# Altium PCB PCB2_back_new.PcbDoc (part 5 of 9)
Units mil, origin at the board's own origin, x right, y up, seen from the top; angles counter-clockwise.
Board outline 6299 x 3937 mil, 4 copper layers (TopLayer, GROUND, VCC, BottomLayer); 253 components, 421 nets, 2085 pads, 712 vias.
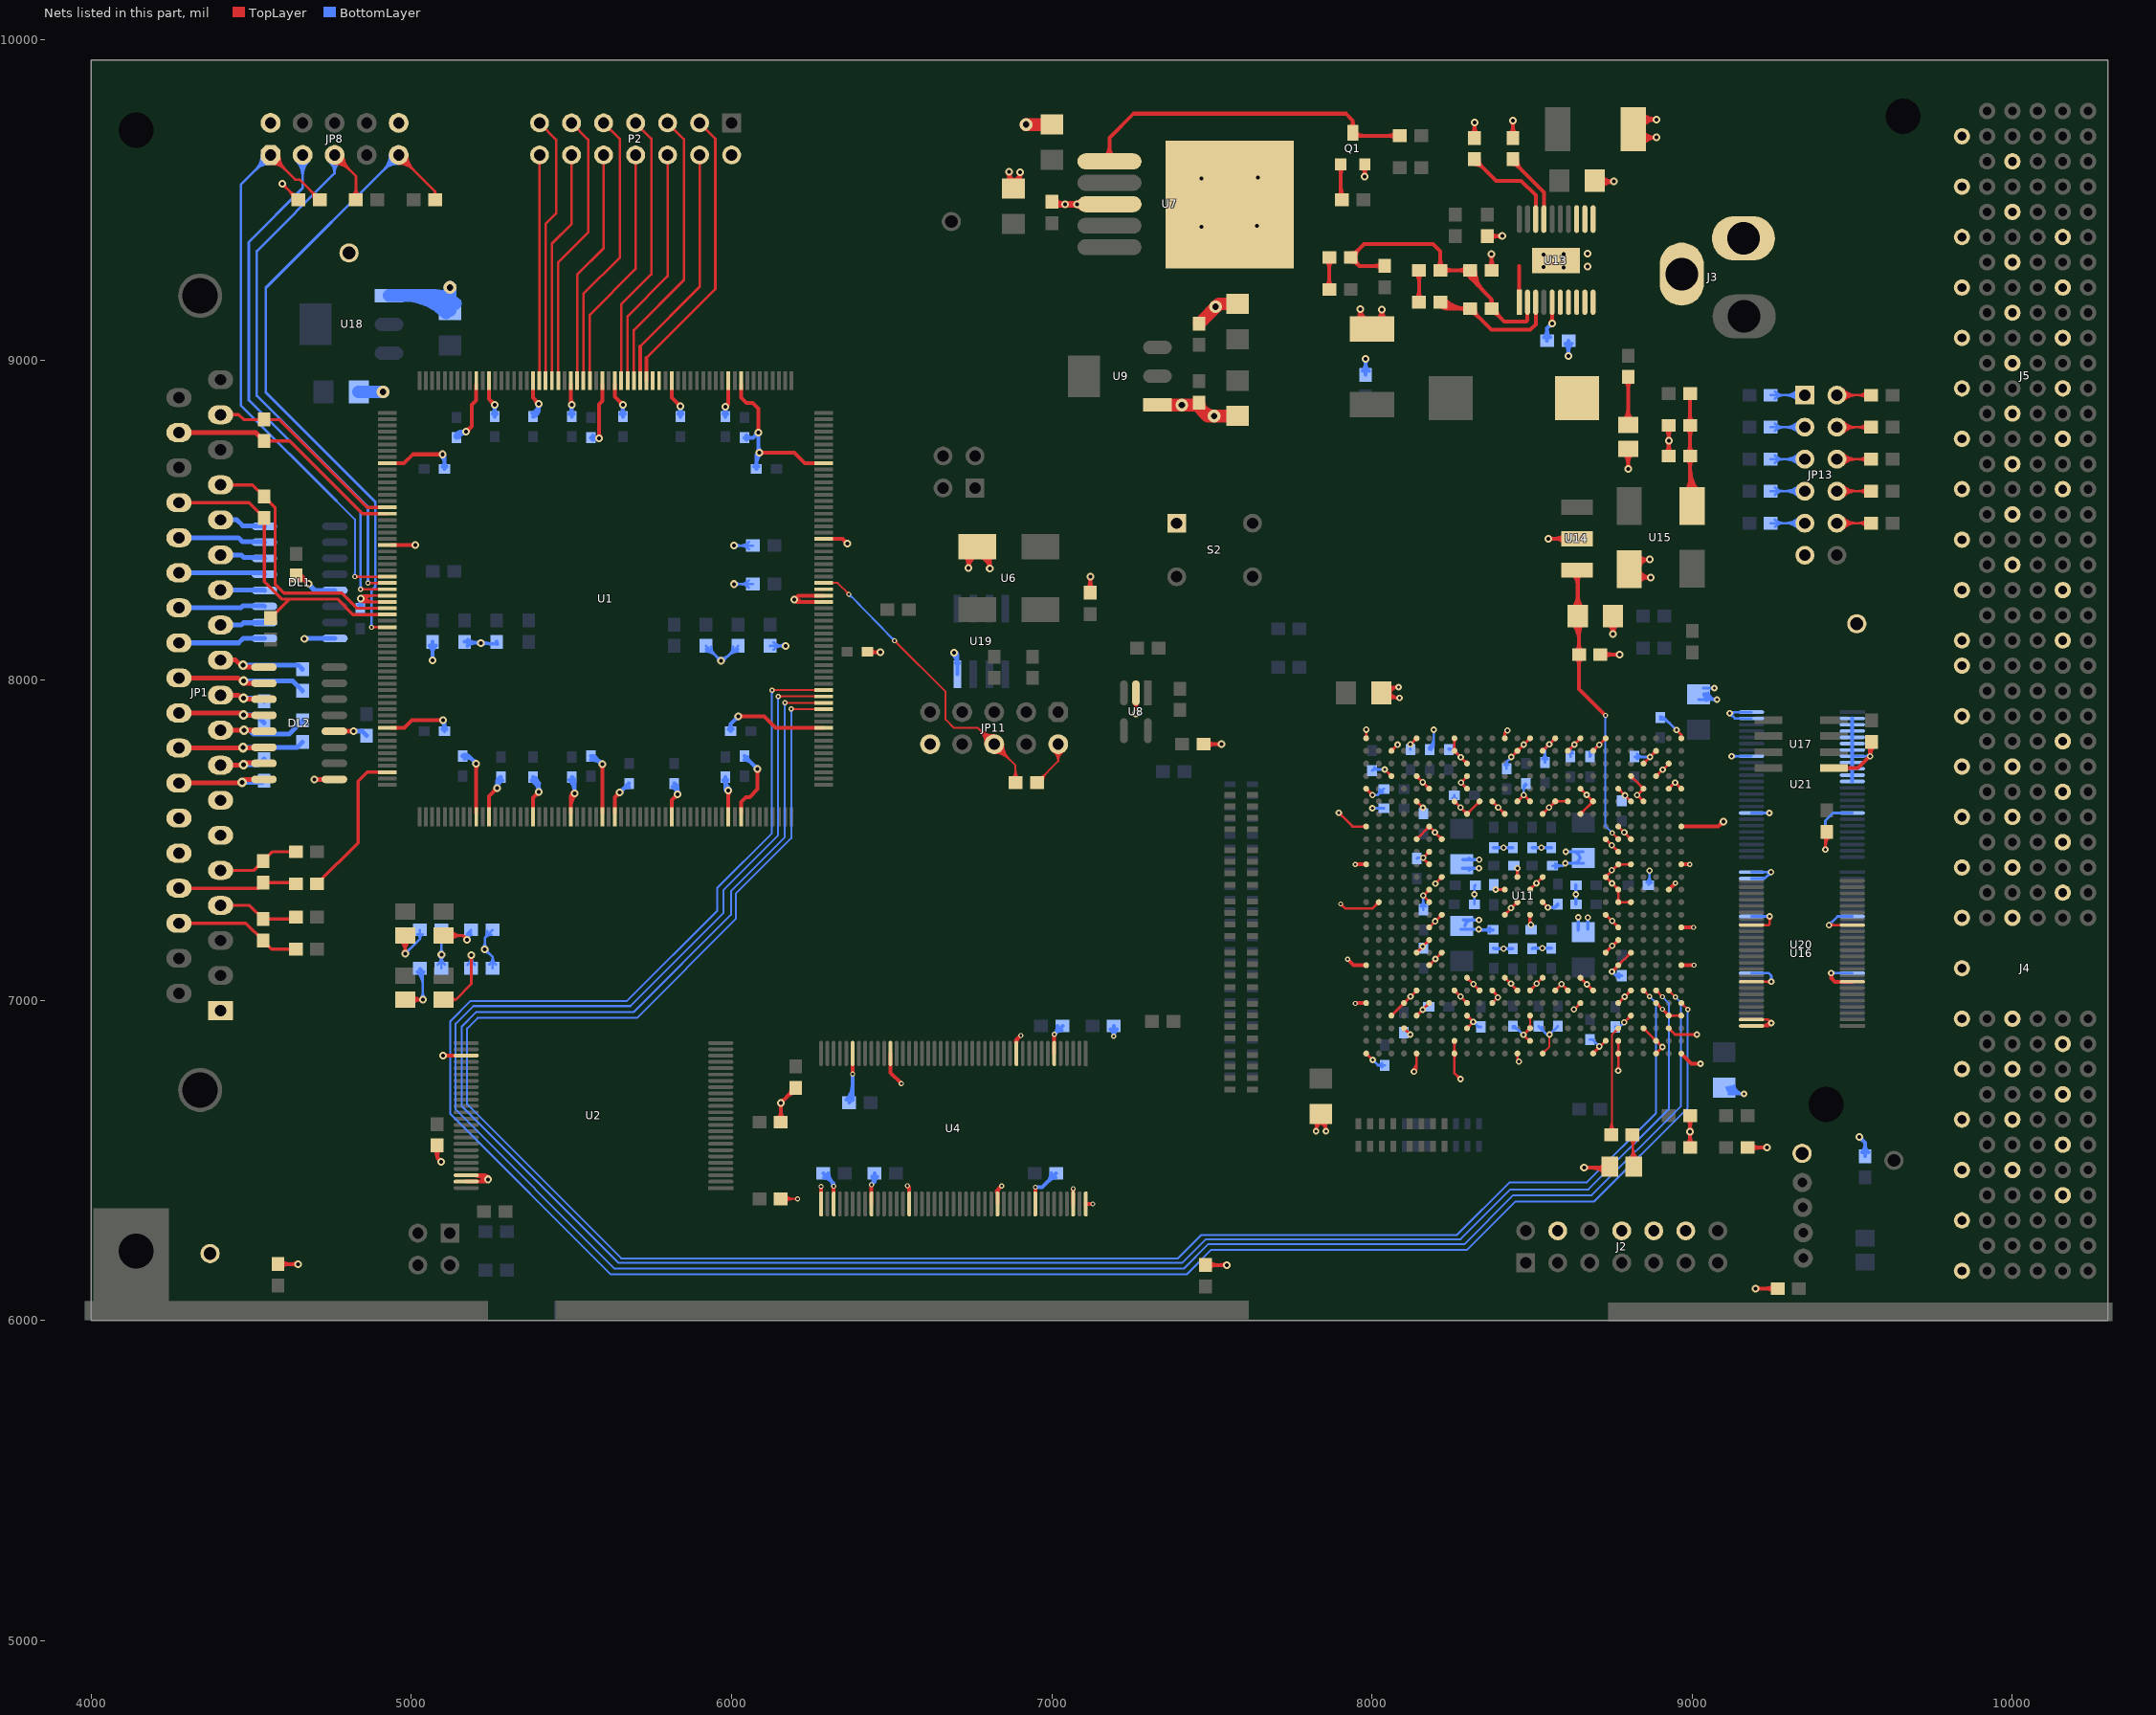
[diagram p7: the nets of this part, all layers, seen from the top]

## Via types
v1: diameter 16, hole 8, TopLayer to BottomLayer, 311 vias
v2: diameter 20, hole 10, TopLayer to BottomLayer, 202 vias
v3: diameter 24, hole 12, TopLayer to BottomLayer, 179 vias
v4: diameter 40, hole 20, TopLayer to BottomLayer, 12 vias
v5: diameter 30, hole 15, TopLayer to BottomLayer, 8 vias

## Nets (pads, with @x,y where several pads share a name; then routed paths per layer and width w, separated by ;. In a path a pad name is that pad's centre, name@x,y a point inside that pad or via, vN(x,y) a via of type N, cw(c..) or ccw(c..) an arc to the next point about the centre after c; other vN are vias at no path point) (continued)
GND: (continued)
  BottomLayer w8: C40.2@4832.8,8233.8 ccw(c4815.64,8253.6) v3@4841.77,8251.73 ; v3@4835.95,8249.76 cw(c4821.36,8237.11) 4840.62,8235.74 cw(c4859.89,8234.36) v3@4847.24,8248.95 ; C40.2@4840,8222.99 4840,8227 v3(4842,8255) ; v3@4841.8,8252.25 ccw(c4868.66,8250.33) C40.2@4848.31,8232.7 ; R88.2@5082.37,7111.09 ccw(c5055.6,7137.87) 5093.46,7137.87 ccw(c5131.33,7137.87) R88.2@5104.56,7111.09 ; R4.2@5082.37,7208.91 cw(c5055.6,7182.13) 5093.46,7182.13 cw(c5131.33,7182.13) R4.2@5104.56,7208.91 ; v3@5087.81,7136.34 cw(c5074.15,7122.69) 5093.46,7122.69 cw(c5112.78,7122.69) v3@5099.12,7136.34 ; v3@5087.81,7147.66 ccw(c5074.15,7161.31) 5093.46,7161.31 ccw(c5112.78,7161.31) v3@5099.12,7147.66 ; R88.2@5093.46,7100 R4.2@5093.46,7220 ; v3@5223.34,7164.66 ccw(c5209.69,7178.31) 5229,7178.31 ccw(c5248.31,7178.31) v3@5234.66,7164.66 ; v3@5229,7151 cw(c5229,7131.69) 5242.66,7145.34 cw(c5256.31,7159) v3@5237,7159 ; R17.2@5236.12,7216.89 cw(c5214.09,7212.42) 5229.99,7196.52 cw(c5248.98,7177.52) R17.2@5250.57,7204.34 ; R16.2@5243.14,7111.81 ccw(c5223.29,7134.53) 5253.46,7134.53 ; R16.2@5253.46,7100 5253.46,7134.54 ; R17.2@5253.46,7220 5229,7195.54 v3(5229,7159) 5253.46,7134.54 ; R16.2@5263.78,7111.81 cw(c5283.64,7134.53) 5253.46,7134.53 ; C68.1@5920,8088.88 cw(c5920,8046.26) 5950.14,8076.4 ; C68.1@5920,8096.88 cw(c5920,8073.58) C68.1@5936.48,8090.06 ; C68.1@5920,8106.54 v3(5966.54,8060) ; C68.1@5935.69,8104.57 ccw(c5968.8,8104.57) 5945.38,8081.15 ; v3@5958.54,8060 ccw(c5939.22,8060) 5952.88,8073.66 ccw(c5966.54,8087.31) 5966.54,8068 ccw(c5966.54,8104.04) 5992.02,8078.56 ; 5978.36,8064.9 cw(c5966.54,8076.73) v3(5966.54,8060) ; 5989.86,8076.4 cw(c6020,8046.26) C72.2@6020,8088.88 ; 5994.62,8081.15 ccw(c5971.2,8104.57) C72.2@6004.31,8104.57 ; C72.2@6003.52,8090.06 cw(c6020,8073.58) C72.2@6020,8096.88 ; v3(6007,8300) R67.1@6066.54,8300 ; v3(6007,8420) R68.1@6066.54,8420 ; v3@6012.66,8294.34 cw(c6026.31,8280.69) 6026.31,8300 cw(c6026.31,8319.31) v3@6012.66,8305.66 ; v3@6012.66,8414.34 cw(c6026.31,8400.69) 6026.31,8420 cw(c6026.31,8439.31) v3@6012.66,8425.66 ; C72.2@6020,8106.54 5973.46,8060 v3(5966.54,8060) ; R67.1@6053.48,8288.91 ccw(c6026.7,8262.13) 6026.7,8300 ccw(c6026.7,8337.87) R67.1@6053.48,8311.09 ; R68.1@6053.48,8408.91 ccw(c6026.7,8382.13) 6026.7,8420 ccw(c6026.7,8457.87) R68.1@6053.48,8431.09 ; C76.1@6120,8106.54 v3(6168,8107) ; C76.1@6130.98,8117.73 ccw(c6157.5,8144.77) 6157.87,8106.9 ccw(c6158.23,8069.04) C76.1@6131.2,8095.55 ; v3@6162.29,8112.6 cw(c6148.5,8126.13) 6148.69,8106.81 cw(c6148.87,8087.5) v3@6162.4,8101.29 ; C91.2@8000,7717.01 8003.99,7721 v2(8039.63,7721) ; v2(8001,7600) C95.2@8037.01,7600 ; v2(8001.52,7641) 8017.09,7641 C96.2@8036.87,7660.77 ; v2(8002,6813.75) 8018.74,6797.01 ; C91.2@8007.78,7727.29 ccw(c8022.95,7742.46) 8022.95,7721 ; 8017.89,7641.79 ccw(c8003.69,7655.99) C96.2@8023.6,7658.58 ; 8018.44,7642.34 cw(c8034.51,7626.27) C96.2@8034.51,7649 ; C93.2@8031.02,6790.65 ccw(c8018.74,6781.96) 8018.74,6797.01 ; C93.2@8031.02,6803.36 cw(c8018.74,6812.05) 8018.74,6797.01 ; C93.2@8040,6797.01 8018.74,6797.01 ; C97.2@8120,7782.99 v2(8120,7799.02) ; C101.2@8140,7442.99 8142.01,7445 v2(8159.68,7445) ; C100.2@8152.22,7293.27 ccw(c8133.44,7312.05) 8160,7312.05 ccw(c8186.56,7312.05) C100.2@8167.78,7293.27 ; C100.2@8160,7282.99 v2(8160,7327) ; C103.2@8177.88,7787.61 ccw(c8141.37,7824.12) 8193,7824.12 ; C103.2@8180,7782.99 8193,7795.99 v2(8193,7845) ; C103.2@8183.54,7781.96 ccw(c8160.69,7804.81) 8193,7804.81 ; C109.2@8239.95,7785.49 cw(c8240.19,7760.58) 8257.8,7778.2 ; C109.2@8240,7782.99 8253.01,7782.99 v2(8277,7759) ; C108.2@8251.86,7630.28 cw(c8247.34,7621.73) 8257.01,7621.73 ; C108.2@8252.36,7631.64 cw(c8243.76,7621.56) 8257.01,7621.56 cw(c8265.35,7621.56) C108.2@8262.83,7629.51 ; C108.2@8257.01,7640 8257.01,7621.73 ; C108.2@8262.15,7630.28 ccw(c8266.68,7621.73) 8257.01,7621.73 ; v2(8276.34,7602.4) 8257.01,7621.73 ; v2(8316,6932.82) 8331.81,6917.01 C110.2@8340,6917.01 ; C105.1@8320,7300 8320,7357.01 C107.2@8322.99,7360 ; C116.2@8414.44,7734.98 ccw(c8408.74,7744.69) 8420,7744.69 ; C116.2@8420,7722.99 8420,7744.69 ; C116.2@8425.56,7734.98 cw(c8431.26,7744.69) 8420,7744.69 ; v2(8435,7759.69) 8420,7744.69 ; C119.2@8440,6913.51 cw(c8440,6886.2) 8459.31,6905.51 ; C119.2@8440,6919.01 8445.81,6919.01 v2(8472.82,6892) ; v2(8473.79,7641) 8473.79,7670.79 C127.2@8480,7677.01 ; 8473.79,7656.27 cw(c8493.45,7656.27) C127.2@8481.78,7672.09 ; C120.2@8520.99,6919.01 C120.2@8520,6919.01 8546.01,6893 v2(8553.99,6893) C128.2@8580,6919.01 ; C120.2@8531,6916.51 ccw(c8551.52,6916.51) 8537.01,6902 ; C132.2@8532.22,7753.27 ccw(c8513.44,7772.05) 8540,7772.05 ccw(c8566.56,7772.05) C132.2@8547.78,7753.27 ; C132.2@8540,7742.99 8540,7785.95 v2(8553.41,7799.37) ; C124.2@8562.99,7420 8596,7420 v2(8604,7428) ; C124.2@8573.27,7412.22 cw(c8592.05,7393.44) 8592.05,7420 cw(c8592.05,7446.56) C124.2@8573.27,7427.78 ; C133.2@8612.89,7771.89 ccw(c8599.93,7787.21) 8620,7787.21 ; C133.2@8620,7760.99 8620,7787.21 ; C133.2@8627.11,7771.89 cw(c8640.07,7787.21) 8620,7787.21 ; v2(8631.67,7798.88) 8620,7787.21 ; C134.2@8680,6877.01 8689.83,6877.01 v2(8710,6856) ; C139.2@8680,7760.99 8680,7768.47 v2(8709.82,7798.29) ; C139.2@8680,7774.49 ccw(c8680,7789.02) 8690.28,7778.75 ; C139.2@8683,7763.49 cw(c8702.27,7763.49) C139.2@8688.64,7777.12 ; C140.2@8760,6917.01 8773.42,6917.01 v2(8787.41,6931) ; C144.2@8820,7760.99 8820.99,7760 v2(8868,7760) ; C144.2@8827.78,7753.21 cw(c8844.16,7736.83) 8844.16,7760 ; C144.2@8827.78,7768.77 ccw(c8848.95,7789.94) 8848.95,7760 ; C142.2@8857.71,7367.78 ccw(c8835.3,7390.2) 8867,7390.2 ; C142.2@8867,7364.01 v2(8867,7405) ; 8867,7382.92 ccw(c8888.41,7382.92) C142.2@8873.27,7367.78 ; C145.2@8900,7877.49 cw(c8900,7835.22) 8929.89,7865.11 ; C145.2@8900,7882.99 8912.01,7882.99 v2(8951,7844) ; C145.2@8900,7885.49 cw(c8900,7862.54) 8916.23,7878.77 ; C146.2@9020,7939 v2(9077,7939) cw(c9077,7965.59) C146.2@9050.91,7960.44 ; C146.2@9034,7975 v2(9069,7975) ; C146.2@9035.22,7957.34 ccw(c9057.53,7961.75) 9057.53,7939 ; C146.2@9043.06,7958.89 ccw(c9067.27,7963.67) v2@9067.27,7939 ; C146.2@9043.38,7935.68 cw(c9051.41,7927.65) C146.2@9051.41,7939 ; v2@9064.76,7970.76 ccw(c9054.51,7960.51) 9054.51,7975 ccw(c9054.51,7989.49) v2@9064.76,7979.24 ; v2@9072.76,7934.76 ccw(c9062.51,7924.51) 9062.51,7939 ccw(c9062.51,7953.49) v2@9072.76,7943.24 ; C147.2@9107.35,6727.95 ccw(c9132.15,6733.39) C147.2@9132.15,6708 ; C147.2@9114,6708 v2(9162,6708) cw(c9162,6739.95) C147.2@9130.79,6733.1 ; C147.2@9115.17,6729.66 ccw(c9142.1,6735.58) 9142.1,6708 ; v2@9117,7891 cw(c9117,7876.51) 9127.24,7886.76 cw(c9137.49,7897) v2@9123,7897 ; v2@9121.24,7892.76 cw(c9138.73,7875.27) 9138.73,7900 ; v2(9122.8,7762.2) U21.41@9185.04,7762.2 ; C147.2@9122.98,6731.38 ccw(c9152.05,6737.76) v2@9152.05,6708 ; v2@9127.04,7757.96 cw(c9137.28,7747.72) 9137.28,7762.2 cw(c9137.28,7776.69) v2@9127.04,7766.45 ; v2@9157.76,6703.76 ccw(c9147.51,6693.51) 9147.51,6708 ccw(c9147.51,6722.49) v2@9157.76,6712.24 ; U20.32@9185.04,7085.04 9238.96,7085.04 9247.2,7076.8 v2(9247.2,7057.8) ; U20.41@9185.04,7262.2 v2(9242.2,7262.2) ; U20.47@9185.04,7380.31 9226.32,7380.31 v2(9246,7400) U20.48@9185.04,7400 ; U21.32@9185.04,7585.04 v2(9240.96,7585.04) ; U21.47@9185.04,7880.31 9133.68,7880.31 v2(9117,7897) 9120,7900 U21.48@9185.04,7900 ; U20.47@9218.9,7381.83 ccw(c9218.9,7403.38) 9234.14,7388.14 ; v2@9236.72,7580.8 ccw(c9226.47,7570.55) 9226.47,7585.04 ccw(c9226.47,7599.53) v2@9236.72,7589.28 ; v2@9237.96,7257.96 ccw(c9227.72,7247.72) 9227.72,7262.2 ccw(c9227.72,7276.69) v2@9237.96,7266.45 ; v2@9240,7400 cw(c9225.51,7400) 9235.76,7389.76 cw(c9246,7379.51) v2@9246,7394 ; v2@9241.76,7395.76 ccw(c9231.51,7385.51) 9231.51,7400 ccw(c9231.51,7414.49) v2@9241.76,7404.24 ; v2@9242.96,7062.04 ccw(c9232.72,7072.28) 9247.2,7072.28 ccw(c9261.69,7072.28) v2@9251.45,7062.04 ; v2@9411.76,7475.24 ccw(c9401.51,7485.49) 9416,7485.49 ccw(c9430.49,7485.49) v2@9420.24,7475.24 ; v2(9416,7471) 9416,7561 9440.04,7585.04 U21.17@9500,7585.04 ; v2(9427.04,7234.96) 9454.28,7262.2 U20.8@9500,7262.2 ; v2@9427.04,7240.96 ccw(c9427.04,7255.45) 9437.28,7245.2 ccw(c9447.53,7234.96) v2@9433.04,7234.96 ; v2(9434.04,7085.04) U20.17@9500,7085.04 ; v2@9438.28,7080.8 cw(c9448.53,7070.55) 9448.53,7085.04 cw(c9448.53,7099.53) v2@9438.28,7089.28 ; U21.8@9500,7762.2 v2(9555.2,7762.2) ; v2@9550.96,7757.96 ccw(c9540.72,7747.72) 9540.72,7762.2 ccw(c9540.72,7776.69) v2@9550.96,7766.45
  BottomLayer w10: C104.2@8277,7222 v2(8333,7222) 8335,7220 C112.1@8378,7220 ; C106.2@8282,7412 v2(8334,7412) ; C106.2@8284,7439 v2(8335,7439) ; C104.2@8285,7251 v2(8334,7251) ; C104.2@8290.39,7232.07 cw(c8311.6,7229.66) C104.2@8311.6,7251 ; C106.2@8302.67,7406.15 cw(c8316.8,7392.01) 8316.8,7412 ; C106.2@8302.67,7443.62 ccw(c8313.82,7454.76) C106.2@8313.82,7439 ; C112.1@8368.43,7212.93 ccw(c8351.36,7195.86) 8351.36,7220 ccw(c8351.36,7244.14) C112.1@8368.43,7227.07 ; C111.2@8380,7162.99 8382,7160.99 C122.2@8440,7160.99 ; C115.2@8380,7477.01 C126.2@8440,7477.01 ; C121.2@8500,7160.99 8502,7162.99 C129.2@8560,7162.99 ; C125.2@8500,7477.01 C131.2@8560,7477.01 ; v2(8549.37,7290) 8570,7290 C130.1@8580,7300 ; C130.1@8566.87,7290 ccw(c8566.87,7305.24) C130.1@8580,7297.5 ; v2(8604,7428) C138.2@8660,7428 ; v2(8605,7464) C138.2@8659,7464 ; C138.2@8627.39,7464 cw(c8627.39,7441.64) C138.2@8649.61,7444.15 ; C138.2@8628.01,7428 ccw(c8628.01,7450.03) C138.2@8649.67,7446.05 ; C136.2@8637.01,7300 C137.2@8637.01,7360 ; C135.2@8644,7220 v2(8644,7259) ; C135.2@8674,7222 v2(8674,7258) ; v2(8749.56,7090) 8762.55,7077.01 ; C141.2@8771.37,7071.95 ccw(c8762.55,7066.79) 8762.55,7077.01 ; C141.2@8771.37,7082.06 cw(c8762.55,7087.23) 8762.55,7077.01 ; C141.2@8780,7077.01 8762.55,7077.01
  BottomLayer w12: C42.1@5056.32,8107.89 cw(c5032.96,8084.53) 5066,8084.53 cw(c5099.04,8084.53) C42.1@5075.68,8107.89 ; v3@5061.76,8065.24 ccw(c5051.51,8075.49) 5066,8075.49 ccw(c5080.49,8075.49) v3@5070.24,8065.24 ; v3(5066,8061) C42.1@5066,8119.54 ; v3@5092.76,8700.76 cw(c5068.05,8676.05) 5102.99,8676.05 ; v3@5094.76,7870.76 cw(c5074.88,7850.88) C45.2@5102.99,7850.88 ; C45.2@5096.63,7846.36 ccw(c5081.26,7861.73) 5102.99,7861.73 ccw(c5124.72,7861.73) C45.2@5109.36,7846.36 ; C47.2@5096.63,8666.36 ccw(c5081.26,8681.73) 5102.99,8681.73 ccw(c5124.72,8681.73) C47.2@5109.36,8666.36 ; v3(5097,8705) 5102.99,8699.01 C47.2@5102.99,8660 ; v3(5099,7875) 5102.99,7871.01 C45.2@5102.99,7840 ; C48.2@5137.06,8760.09 cw(c5156.41,8756.28) 5156.41,8776 ; C48.2@5140,8757.01 5158.99,8776 ; C48.2@5140.26,8757.27 cw(c5171,8726.52) v3@5171,8770 ; C48.2@5140.23,8768.51 ccw(c5140.88,8794.11) 5158.99,8776 ; C48.2@5148.83,8757.77 cw(c5171,8753.41) v3(5171,8776) 5158.99,8776 ; C48.2@5149,8759.51 cw(c5164.69,8759.51) C48.2@5153.6,8770.6 ; C44.2@5158.11,7762.82 cw(c5168.58,7749.9) 5180.34,7761.66 ; C44.2@5160,7763.49 cw(c5160,7718.81) 5191.6,7750.4 ; C44.2@5165.67,7753.5 cw(c5177.01,7739.49) 5189.76,7752.24 ; C46.1@5166,8119.54 v3(5217,8116) 5267,8112 C50.2@5266,8119.54 ; C46.1@5174.98,8107.24 cw(c5201.08,8077.27) 5203.82,8116.91 ; C46.1@5176.32,8126.55 ccw(c5196.19,8143.84) 5194.37,8117.57 ; 5179.01,7762.99 v3(5202.46,7739.54) ; v3@5196.46,7739.54 ccw(c5181.97,7739.54) 5192.21,7749.79 ccw(c5202.46,7760.03) v3@5202.46,7745.54 ; v3@5212.47,8112.06 ccw(c5201.55,8102.55) 5202.55,8117 ccw(c5203.55,8131.45) v3@5213.06,8120.53 ; v3@5220.89,8111.43 cw(c5230.28,8100.41) 5231.44,8114.84 cw(c5232.59,8129.28) v3@5221.57,8119.89 ; C51.2@5253.64,8831.86 ccw(c5238.27,8847.22) 5260,8847.22 ccw(c5281.73,8847.22) C51.2@5266.36,8831.86 ; v3@5255.76,8854.76 cw(c5245.51,8844.51) 5260,8844.51 cw(c5274.49,8844.51) v3@5264.24,8854.76 ; C51.2@5260,8822.99 v3(5260,8859) ; v3@5262.76,7667.24 ccw(c5252.51,7677.49) 5267,7677.49 ccw(c5281.49,7677.49) v3@5271.24,7667.24 ; v3@5267,7660.42 cw(c5295.4,7660.42) C49.2@5283.71,7686.31 ; v3(5267,7663) 5267,7684.01 C49.2@5280,7697.01 ; 5267,7679.02 cw(c5287,7679.02) C49.2@5278.76,7697.24 ; C52.2@5375.45,7686.74 cw(c5352.45,7647.43) v3@5398,7647.43 ; C53.2@5377.06,8834 ccw(c5367.37,8862) v3(5397,8862) 5397,8839.99 ; C52.2@5380,7697.01 5398,7679.01 v3(5398,7651) ; C53.2@5380,8822.99 5397,8839.99 ; C52.2@5380.13,7685.51 cw(c5380.53,7659.04) 5399.25,7677.76 ; C53.2@5380.98,8822.66 ccw(c5373.2,8845.15) 5397,8845.15 ; C53.2@5381.03,8834.43 ccw(c5383.27,8853.72) 5397,8839.99 ; C52.2@5381.52,7697.1 cw(c5364.69,7668.35) 5398,7668.35 ; C52.2@5389,7694.51 ccw(c5404.69,7694.51) C52.2@5393.6,7683.41 ; C53.2@5389,8825.49 cw(c5404.69,8825.49) C53.2@5393.6,8836.59 ; v3@5392.76,8857.76 cw(c5382.51,8847.51) 5397,8847.51 cw(c5411.49,8847.51) v3@5401.24,8857.76 ; v3@5393.76,7655.24 ccw(c5383.51,7665.49) 5398,7665.49 ccw(c5412.49,7665.49) v3@5402.24,7655.24 ; C54.2@5493.64,7688.14 cw(c5456.54,7651.05) v3@5509,7651.05 ; C58.2@5493.64,8831.86 ccw(c5478.27,8847.22) 5500,8847.22 ccw(c5521.73,8847.22) C58.2@5506.36,8831.86 ; v3@5495.76,8855.76 cw(c5485.51,8845.51) 5500,8845.51 cw(c5514.49,8845.51) v3@5504.24,8855.76 ; C54.2@5500,7697.01 5509,7688.01 v3(5509,7646) ; C58.2@5500,8822.99 v3(5500,8860) ; C54.2@5502.12,7696.63 cw(c5485.52,7680.02) C54.2@5509,7680.02 ; v3@5504.76,7650.24 ccw(c5494.51,7660.49) 5509,7660.49 ccw(c5523.49,7660.49) v3@5513.24,7650.24 ; C56.2@5560,7751.49 cw(c5560,7699.57) v3@5596.72,7736.28 ; C56.2@5560,7762.99 5570.01,7762.99 v3(5596.16,7736.84) ; C56.2@5560,7763.49 cw(c5560,7740.54) 5576.23,7756.77 ; C57.2@5560,8757.01 5583.99,8757.01 v3(5586,8755) ; C57.2@5566.36,8750.64 cw(c5581.73,8735.28) 5581.73,8757.01 cw(c5581.73,8778.74) C57.2@5566.36,8763.37 ; C57.2@5566.67,8757.01 cw(c5566.67,8735.67) v3@5581.76,8750.76 ; v3@5590.16,7736.84 ccw(c5575.67,7736.84) 5585.91,7747.09 ccw(c5596.16,7757.33) v3@5596.16,7742.84 ; v3(5650,7649) 5678.01,7677.01 C60.2@5680,7677.01 ; v3@5650,7655 ccw(c5650,7669.49) 5660.24,7659.24 ccw(c5670.49,7649) v3@5656,7649 ; C61.2@5653.64,8831.86 ccw(c5638.27,8847.22) 5660,8847.22 ccw(c5681.73,8847.22) C61.2@5666.36,8831.86 ; v3@5655.76,8855.76 cw(c5645.51,8845.51) 5660,8845.51 cw(c5674.49,8845.51) v3@5664.24,8855.76 ; v3@5656.97,7655.97 cw(c5680,7632.94) C60.2@5680,7665.51 ; C61.2@5660,8822.99 v3(5660,8860) ; C63.2@5815.76,7666.57 cw(c5802.16,7641.14) v3@5831,7641.14 ; C63.2@5820,7677.01 5831,7666.01 v3(5831,7643) ; C63.2@5821.41,7677.15 cw(c5812.86,7661.16) C63.2@5831,7661.16 ; v3@5826.76,7647.24 ccw(c5816.51,7657.49) 5831,7657.49 ccw(c5845.49,7657.49) v3@5835.24,7647.24 ; C64.2@5833.64,8831.86 ccw(c5818.27,8847.22) 5840,8847.22 ccw(c5861.73,8847.22) C64.2@5846.36,8831.86 ; v3@5835.76,8850.76 cw(c5825.51,8840.51) 5840,8840.51 cw(c5854.49,8840.51) v3@5844.24,8850.76 ; C64.2@5840,8822.99 v3(5840,8855) ; C67.2@5973.64,7688.14 cw(c5958.27,7672.78) 5980,7672.78 cw(c6001.73,7672.78) C67.2@5986.36,7688.14 ; C69.2@5973.64,8831.86 ccw(c5958.27,8847.22) 5980,8847.22 ccw(c6001.73,8847.22) C69.2@5986.36,8831.86 ; v3@5975.76,8849.76 cw(c5965.51,8839.51) 5980,8839.51 cw(c5994.49,8839.51) v3@5984.24,8849.76 ; 5980,7664.46 ccw(c5999.17,7664.46) v3@5985.62,7650.9 ; C67.2@5980,7693.43 ccw(c6028.14,7693.43) v3@5994.1,7659.38 ; C67.2@5980,7697.01 5980,7665 ; C69.2@5980,8822.99 v3(5980,8854) ; v3@5983.86,7655.31 ccw(c5970.67,7655.67) 5980,7665 ; v3@5989.69,7661.14 cw(c5989.33,7674.33) 5980,7665 ; v3(5989.86,7655.14) 5980,7665 ; C71.2@5990.64,7846.36 ccw(c5975.28,7861.73) 5997.01,7861.73 ccw(c6018.74,7861.73) C71.2@6003.37,7846.36 ; C71.2@5997.01,7840 5997.01,7863.01 v3(6021,7887) ; v3@6015,7887 cw(c6000.51,7887) 6010.76,7876.76 cw(c6021,7866.51) v3@6021,7881 ; C75.2@6040,7751.49 cw(c6040,7723.73) 6059.63,7743.36 ; C75.2@6040,7762.99 v3(6081,7721.99) ; C77.2@6040,8757.01 6067.01,8757.01 v3(6083,8773) 6083,8710 v3(6086,8710) 6077.01,8701.01 ; C77.2@6046.36,8750.64 cw(c6061.73,8735.28) 6061.73,8757.01 cw(c6061.73,8778.74) C77.2@6046.36,8763.37 ; C75.2@6049,7760.49 ccw(c6064.69,7760.49) C75.2@6053.6,7749.4 ; C73.2@6070.64,8666.36 ccw(c6055.28,8681.73) 6077.01,8681.73 ccw(c6098.74,8681.73) C73.2@6083.37,8666.36 ; v3@6075,7721.99 ccw(c6060.51,7721.99) 6070.76,7732.23 ccw(c6081,7742.48) v3@6081,7727.99 ; C73.2@6077.01,8660 6077.01,8701.01 ; C73.2@6077.01,8673.81 cw(c6122.19,8673.81) v3@6090.24,8705.76 ; v3@6077,8773 cw(c6062.51,8773) 6072.76,8762.76 cw(c6083,8752.51) v3@6083,8767 ; v3@6078.76,8768.76 cw(c6068.51,8758.51) 6083,8758.51 cw(c6097.49,8758.51) v3@6087.24,8768.76 ; v3@6080.03,8709.42 cw(c6069.6,8708.42) 6077.01,8701.01 ; 6083,8731.73 ccw(c6107.73,8731.73) v3@6090.24,8714.24 ; v3@6085.42,8704.03 ccw(c6084.42,8693.6) 6077.01,8701.01 ; C79.1@6286.54,6460 6318.6,6427.94 v1(6318.6,6419.4) ; C79.1@6288.5,6446.32 cw(c6288.5,6418.03) 6308.51,6438.03 ; C79.1@6302.19,6460 ccw(c6339.98,6460) 6313.26,6433.28 ; 6309.15,6437.39 cw(c6291.17,6419.4) v1@6316.6,6419.4 ; C80.1@6358.83,6689.68 ccw(c6313.37,6735.13) 6377.65,6735.13 ; C80.1@6367.31,6681.19 ccw(c6342.34,6706.16) 6377.65,6706.16 ; C80.1@6377.65,6688.88 v1(6377.65,6769.35) ; v1@6435.3,6425.12 ccw(c6408.16,6452.26) C81.1@6446.54,6452.26 ; v1(6436.71,6423.71) 6446.54,6433.54 ; C81.1@6438.63,6448.83 cw(c6427.79,6433.54) 6446.54,6433.54 ; C81.1@6446.54,6460 6446.54,6433.54 ; C81.1@6454.45,6448.83 ccw(c6465.28,6433.54) 6446.54,6433.54 ; v3@6690.76,8080.76 cw(c6656.37,8046.37) U19.4@6705,8046.37 ; v3(6695,8085) 6705,8075 ; v3@6695.1,8079 cw(c6695.34,8065.34) 6705,8075 ; v3@6699.24,8089.24 cw(c6685.34,8075.34) 6705,8075.34 ; U19.4@6700.89,8053.24 ccw(c6690.97,8063.16) 6705,8063.16 ccw(c6719.03,8063.16) U19.4@6709.11,8053.24 ; v3@6701,8084.9 ccw(c6714.66,8084.66) 6705,8075 ; U19.4@6705,8017.64 6705,8075 ; v1(6948.52,6416.52) 6969.98,6416.52 C82.1@7013.46,6460 ; 6986.74,6433.28 ccw(c6960.02,6460) C82.1@6997.81,6460 ; 6991.49,6438.03 cw(c7011.5,6418.03) C82.1@7011.5,6446.32 ; v1(7007.57,6894.11) C83.1@7033.46,6920 ; v1@7008.56,6895.1 ccw(c6986.07,6917.58) C83.1@7017.83,6919.27 ; v1@7011.49,6898.03 cw(c7031.5,6878.03) C83.1@7031.5,6906.32 ; C84.1@7183.89,6910.22 cw(c7161.64,6887.47) v1(7193.46,6887.46) ; C84.1@7193.46,6920 v1(7193.46,6887.46) ; C84.1@7203.03,6910.22 ccw(c7225.29,6887.47) v1(7193.46,6887.46) ; C92.1@7970.32,8965.11 ccw(c7946.96,8988.47) 7980,8988.47 ccw(c8013.04,8988.47) C92.1@7989.68,8965.11 ; v3@7975.76,8998.76 cw(c7965.51,8988.51) 7980,8988.51 cw(c7994.49,8988.51) v3@7984.24,8998.76 ; C92.1@7980,8953.46 v3(7980,9003) ; U21.12@9500,7683.47 U21.2@9500,7880.31 ; v3@9522,6567 cw(c9522,6552.51) 9532.24,6562.76 cw(c9542.49,6573) v3@9528,6573 ; v3(9522,6573) 9540,6555 R103.2@9540,6513.46 ; R103.2@9530.32,6525.11 ccw(c9506.96,6548.47) 9540,6548.47 ccw(c9573.04,6548.47) R103.2@9549.68,6525.11
  BottomLayer w15: v3@4667,8130.1 DL1.8@4760.7,8130.1 ; v3(4679,8301) 4679,8299.2 4698.1,8280.1 DL1.5@4760.7,8280.1 ; v3(4819,7840) 4846.54,7840 C1.2@4860,7826.54
  BottomLayer w40: C38.2@4835.12,8900 v4(4911,8900) ; U18.1@4930,9201 5074.12,9201 ; 4977.54,9201 cw(c4977.54,9016.6) C43.2@5107.93,9146.99 ; C43.2@5093.65,9181.46 cw(c5067.31,9155.12) C43.2@5104.57,9155.12 ; v4(5120,9226) C43.2@5120,9155.12 5074.12,9201 ; C43.2@5136.22,9175.27 ccw(c5074.11,9113.16) 5074.11,9201
  other v1: 8906.68,6972.06
  other v2: 8158.11,6970.99 8789,7011 8120.43,7012.05 8276.51,7011.68 8316.5,7050.42 8671,7050 8434,7052 8514,7052 8198.14,7129.13 8411,7160.99 8532,7162.99 8158.45,7168.18 8750,7170 8197,7247 8750,7248 8434,7288 8320,7331 8637.01,7331 8749.46,7365.5 8513.29,7365.54 8749,7406 8411,7477.01 8529,7477.01 8748.71,7484.36 8788,7524 8196.61,7524.65 8394,7602 8553.21,7602.31 8790,7640 8670.04,7641.77 8158.49,7680.88 8907.77,7720.65
  other v3: 8993.47,6590 5093.46,7142 4666,8129 8926.54,8747 8599,9288 8536,9290 8673,9292 8535,9329 8599,9330 8673,9332 7467,9415 7641,9419 7042,9486 7078,9486 7467,9567 7643,9569
  other v4: 7406,8859
GP02: R51.1 U11.C6 | length 469.6
  TopLayer w6: R51.1@8736.71,6591.8 ccw(c8707.03,6621.48) 8749,6621.48 ; R51.1@8740.95,6587.56 ccw(c8721.51,6606.99) 8749,6606.99 ; R51.1@8746.54,6580 8749,6582.46 8749,6892.59 U11.C6@8769.15,6912.74 ; 8749,6604.6 ccw(c8773.1,6604.6) R51.1@8756.06,6587.56 ; 8749,6619.08 ccw(c8787.59,6619.08) R51.1@8760.3,6591.8 ; U11.C6@8762.9,6912.74 cw(c8747.8,6912.74) 8758.48,6902.07 cw(c8769.15,6891.39) U11.C6@8769.15,6906.49
GP04: U1.13 U11.F4 | length 6605.1
  TopLayer w6: v1(6186,7909.51) U1.13@6274.31,7909.51 ; v1@6189.54,7905.98 cw(c6198.07,7897.44) 6198.07,7909.51 cw(c6198.07,7921.58) v1@6189.54,7913.05 ; U1.13@6261.43,7907.46 ccw(c6256.47,7902.5) 6256.47,7909.51 ccw(c6256.47,7916.53) U1.13@6261.43,7911.57 ; U11.F4@8847.89,7024.6 cw(c8847.89,7009.51) 8858.56,7020.18 cw(c8869.24,7030.85) U11.F4@8854.14,7030.85 ; U11.F4@8847.89,7030.85 v1(8867,7011.74)
  BottomLayer w6: v1@6182.46,7905.98 cw(c6173.93,7897.44) 6186,7897.44 cw(c6198.07,7897.44) v1@6189.54,7905.98 ; v1(6186,7909.51) 6186,7506 6013,7333 6013,7254 5704,6945 5207,6945 5174,6912 5174,6675 5655,6194 7394,6194 7467,6267 8265,6267 8430,6432 8671,6432 8887,6648 8887,6991.74 v1(8867,7011.74)
GP05: U1.14 U11.F3 | length 6705.4
  TopLayer w6: v1(6166,7929.2) U1.14@6274.31,7929.2 ; v1@6169.54,7925.66 cw(c6178.07,7917.13) 6178.07,7929.2 cw(c6178.07,7941.27) v1@6169.54,7932.73 ; U1.14@6261.43,7927.14 ccw(c6256.47,7922.18) 6256.47,7929.2 ccw(c6256.47,7936.21) U1.14@6261.43,7931.25 ; U11.F3@8887.26,7024.6 cw(c8887.26,7009.51) 8897.93,7020.18 cw(c8908.61,7030.85) U11.F3@8893.51,7030.85 ; U11.F3@8887.26,7030.85 v1(8907,7011.11)
  BottomLayer w6: v1@6162.46,7925.66 cw(c6153.93,7917.13) 6166,7917.13 cw(c6178.07,7917.13) v1@6169.54,7925.66 ; v1(6166,7929.2) 6166,7509 5998,7341 5998,7267 5695,6964 5203,6964 5157,6918 5157,6670 5647,6180 7407,6180 7481,6254 8277,6254 8432,6409 8676,6409 8927,6660 8927,6991.11 v1(8907,7011.11)
GP06: U1.15 U11.F2 | length 6816.6
  TopLayer w6: v1(6145,7948.88) U1.15@6274.31,7948.88 ; v1@6148.54,7945.35 cw(c6157.07,7936.81) 6157.07,7948.88 cw(c6157.07,7960.95) v1@6148.54,7952.42 ; U1.15@6261.43,7946.83 ccw(c6256.47,7941.87) 6256.47,7948.88 ccw(c6256.47,7955.9) U1.15@6261.43,7950.94 ; U11.F2@8926.63,7024.6 cw(c8926.63,7009.51) 8937.3,7020.18 cw(c8947.98,7030.85) U11.F2@8932.88,7030.85 ; U11.F2@8926.63,7030.85 v1(8947,7010.48)
  BottomLayer w6: v1@6141.46,7945.35 cw(c6132.93,7936.81) 6145,7936.81 cw(c6157.07,7936.81) v1@6148.54,7945.35 ; v1(6145,7948.88) 6145,7515 5974,7344 5974,7272 5684,6982 5193,6982 5138,6927 5138,6659 5635,6162 7412,6162 7488,6238 8288,6238 8441.27,6391.27 8686.27,6391.27 8965,6670 8965,6992.48 v1(8947,7010.48)
GP07: U1.16 U11.E1 | length 6869.8
  TopLayer w6: v1(6126,7968.57) U1.16@6274.31,7968.57 ; v1@6129.54,7965.03 cw(c6138.07,7956.5) 6138.07,7968.57 cw(c6138.07,7980.64) v1@6129.54,7972.1 ; U1.16@6261.43,7966.51 ccw(c6256.47,7961.55) 6256.47,7968.57 ccw(c6256.47,7975.58) U1.16@6261.43,7970.62 ; U11.E1@8966,6985.23 cw(c8966,6970.14) 8976.67,6980.81 cw(c8987.35,6991.48) U11.E1@8972.25,6991.48 ; U11.E1@8966,6991.48 v1(8986,6971.48)
  BottomLayer w6: v1@6122.46,7965.03 cw(c6113.93,7956.5) 6126,7956.5 cw(c6138.07,7956.5) v1@6129.54,7965.03 ; v1(6126,7968.57) 6126,7522 5955,7351 5955,7280 5673,6998 5185,6998 5121,6934 5121,6646 5623,6144 7421,6144 7497,6220 8296,6220 8448.02,6372.02 8694.02,6372.02 8986,6664 v1(8986,6971.48)
IO1: U1.82
IO2: U1.83
IO3: P2.3 U1.84 | length 914.3
  TopLayer w8: 5733.95,9005.95 5949,9221 5949,9691 P2.3@5900,9740
  TopLayer w12: U1.84@5733.95,8935.1 5733.95,9005.95
IO4: P2.4 U1.85 | length 781.8
  TopLayer w8: 5714.27,9042.27 5900,9228 P2.4@5900,9640
  TopLayer w12: U1.85@5714.27,8935.1 5714.27,9042.27
IO5: P2.5 U1.86 | length 890.8
  TopLayer w8: U1.86@5694.58,8935.1 5694.58,9092.58 5851,9249 5851,9689 P2.5@5800,9740
IO6: P2.6 U1.87 | length 756.7
  TopLayer w8: U1.87@5674.9,8935.1 5674.9,9135.9 5800,9261 P2.6@5800,9640
IO7: P2.7 U1.88 | length 864
  TopLayer w8: U1.88@5655.21,8935.1 5655.21,9173.21 5749,9267 5749,9691 P2.7@5700,9740
IO8: P2.8 U1.93 | length 764.2
  TopLayer w8: U1.93@5556.79,8935.1 5556.79,9140.79 5700,9284 P2.8@5700,9640
IO9: P2.9 U1.94 | length 873.2
  TopLayer w8: U1.94@5537.1,8935.1 5537.1,9206.1 5651,9320 5651,9689 P2.9@5600,9740
IO10: P2.10 U1.95 | length 739.1
  TopLayer w8: U1.95@5517.42,8935.1 5517.42,9266.42 5600,9349 P2.10@5600,9640
IO11: P2.11 U1.98 | length 865.2
  TopLayer w8: U1.98@5458.36,8935.1 5458.36,9304.36 5552,9398 5552,9688 P2.11@5500,9740
IO12: P2.12 U1.99 | length 730.3
  TopLayer w8: U1.99@5438.68,8935.1 5438.68,9363.68 5500,9425 P2.12@5500,9640
IO13: P2.13 U1.100 | length 840.1
  TopLayer w8: P2.13@5400,9740 5452,9688 5452,9457 5418.99,9423.99 U1.100@5418.99,8935.1
IO14: P2.14 U1.101 | length 705.2
  TopLayer w8: U1.101@5399.31,8935.1 P2.14@5399.31,9639.31
  TopLayer w12: P2.14@5399.31,9639.31 P2.14@5400,9640
JTAG_TCK: JP8.1 R14.2 U1.147 | length 2289.9
  TopLayer w8: JP8.1@4560,9613 cw(c4560,9547.82) 4606.09,9593.91 cw(c4652.18,9640) JP8.1@4587,9640 ; JP8.1@4560,9621 cw(c4560,9575.13) 4592.44,9607.56 cw(c4624.87,9640) JP8.1@4579,9640 ; JP8.1@4560,9640 4637,9563 4650.46,9563 R14.2@4713.46,9500 ; 4683.33,9530.14 cw(c4653.19,9500) R14.2@4695.81,9500 ; 4688.08,9525.38 ccw(c4711.5,9548.8) R14.2@4711.5,9515.68 ; R14.2@4696.99,9516.48 cw(c4680.51,9500) R14.2@4703.81,9500 ; v1(4823,8323) U1.147@4924.9,8322.9 U1.147@4937.69,8322.9 ; v1@4825.83,8320.17 cw(c4832.65,8313.33) 4832.66,8322.99 cw(c4832.67,8332.65) v1@4825.83,8325.83
  BottomLayer w6: 4766.17,8558.83 4823,8502 v1(4823,8323) ; v1@4819.46,8326.54 ccw(c4810.93,8335.07) 4823,8335.07 ccw(c4835.07,8335.07) v1@4826.54,8326.54
  BottomLayer w8: JP8.1@4533,9640 cw(c4467.82,9640) 4513.91,9593.91 cw(c4560,9547.82) JP8.1@4560,9613 ; JP8.1@4541,9640 cw(c4495.13,9640) 4527.56,9607.56 cw(c4560,9575.13) JP8.1@4560,9621 ; JP8.1@4560,9640 4467,9547 4467,8858 4766.17,8558.83
JTAG_TDI: JP8.9 R18.1 U1.155 | length 2453.6
  TopLayer w8: v1(4875,8165) 4924.9,8165.33 U1.155@4937.69,8165.42 ; v1@4877.81,8167.85 ccw(c4884.59,8174.72) 4884.66,8165.06 ccw(c4884.72,8155.41) v1@4877.85,8162.19 ; JP8.9@4960,9613 cw(c4960,9547.82) 5006.09,9593.91 cw(c5052.18,9640) JP8.9@4987,9640 ; JP8.9@4960,9621 cw(c4960,9575.13) 4992.44,9607.56 cw(c5024.87,9640) JP8.9@4979,9640 ; JP8.9@4960,9640 5073.46,9526.54 ; R18.1@5065.9,9513.74 ccw(c5058.86,9526.53) 5073.46,9526.53 ; R18.1@5073.46,9500 5073.46,9526.54 ; R18.1@5081.03,9513.74 cw(c5088.07,9526.53) 5073.46,9526.53
  BottomLayer w8: v1@4872.17,8167.83 ccw(c4865.34,8174.66) 4875,8174.66 ccw(c4884.66,8174.66) v1@4877.83,8167.83 ; v1(4875,8165) 4875,8279 4887,8291 4887,8557 4545,8899 4545,9225 JP8.9@4960,9640 ; JP8.9@4933,9640 cw(c4867.82,9640) 4913.91,9593.91 cw(c4960,9547.82) JP8.9@4960,9613 ; JP8.9@4941,9640 cw(c4895.13,9640) 4927.56,9607.56 cw(c4960,9575.13) JP8.9@4960,9621
JTAG_TDO: JP8.3 U1.149 | length 1871.6
  TopLayer w8: v1(4841,8284) 4924.9,8283.59 U1.149@4937.69,8283.53 ; v1@4843.81,8281.16 cw(c4850.61,8274.3) 4850.66,8283.95 cw(c4850.7,8293.61) v1@4843.84,8286.81
  BottomLayer w8: JP8.3@4640.91,9620.91 cw(c4594.82,9574.82) 4660,9574.82 cw(c4725.18,9574.82) JP8.3@4679.09,9620.91 ; JP8.3@4646.56,9626.56 cw(c4614.13,9594.13) 4660,9594.13 cw(c4705.87,9594.13) JP8.3@4673.44,9626.56 ; JP8.3@4660,9640 4660,9536 4492,9368 4492,8874 4841,8525 v1(4841,8284) ; v1@4838.17,8286.83 ccw(c4831.34,8293.66) 4841,8293.66 ccw(c4850.66,8293.66) v1@4843.83,8286.83
JTAG_TMS: JP8.5 R15.1 U1.148 | length 2227.6
  TopLayer w8: JP8.5@4760,9613 cw(c4760,9547.82) 4806.09,9593.91 cw(c4852.18,9640) JP8.5@4787,9640 ; JP8.5@4760,9621 cw(c4760,9575.13) 4792.44,9607.56 cw(c4824.87,9640) JP8.5@4779,9640 ; JP8.5@4760,9640 4826.54,9573.46 R15.1@4826.54,9500 ; R15.1@4815.44,9511.09 ccw(c4788.67,9537.87) 4826.54,9537.87 ccw(c4864.4,9537.87) R15.1@4837.63,9511.09 ; v1(4864,8303) U1.148@4924.9,8303.21 U1.148@4937.69,8303.21 ; v1@4866.82,8305.84 ccw(c4873.63,8312.68) 4873.66,8303.03 ccw(c4873.68,8293.37) v1@4866.84,8300.18
  BottomLayer w8: JP8.5@4742.9,9619.11 cw(c4713.34,9583) 4760,9583 ; JP8.5@4747.96,9625.3 cw(c4727.16,9599.89) 4760,9599.89 cw(c4792.84,9599.89) JP8.5@4772.04,9625.3 ; JP8.5@4760,9640 4760,9583 ; JP8.5@4777.1,9619.11 ccw(c4806.66,9583) 4760,9583 ; v1@4861.17,8305.83 ccw(c4854.34,8312.66) 4864,8312.66 ccw(c4873.66,8312.66) v1@4866.83,8305.83 ; v1(4864,8303) 4864,8541 4517,8888 4517,9340 4760,9583
LVDS1_INCLKN: JP1.16 R2.1 U1.152 | length 833
  TopLayer w10: JP1.16@4403.78,8609.76 4503.7,8609.76 R2.1@4540,8573.46 4574,8539.46 4574,8300 4602,8272 4668,8272 ; 4656,8272 4668,8272 ; U1.152@4924.9,8224.47 4830.53,8224.47 4783,8272 4668,8272
LVDS1_INCLKP: JP1.34 R2.2 R96.1 U1.153 | length 996.8
  TopLayer w10: JP1.34@4273.86,8554.04 4492.5,8554.04 R2.2@4540,8506.54 4540,8307 4594,8253 4619.54,8253 ; R96.1@4560,8193.46 4619.54,8253 ; U1.153@4924.9,8204.79 4817.21,8204.79 4769,8253 4619.54,8253
LVDS1_INDATAN: JP1.18 R1.1 U1.136 | length 640.9
  TopLayer w10: JP1.18@4403.78,8828.66 4460.34,8828.66 4475.54,8813.46 R1.1@4540,8813.46 4587.54,8813.46 4861.57,8539.43 U1.136@4924.9,8539.43
LVDS1_INDATAP: JP1.36 R1.2 U1.137 | length 755.9
  TopLayer w10: R1.2@4540,8746.54 4619.46,8746.54 4846.25,8519.75 U1.137@4924.9,8519.75
  TopLayer w15: JP1.36@4273.86,8772.94 4513.6,8772.94 R1.2@4540,8746.54
LVDS_CLK: 
LVIN1+: DL2.2 JP1.29 R10.2 | length 469
  TopLayer w15: JP1.29@4273.86,8006.8 4458.3,8006.8 4475,7990.1 DL2.2@4539.3,7990.1
  BottomLayer w15: v5(4476,7997.1) 4629.44,7997.1 R10.2@4660,7966.54
LVIN1-: DL2.1 JP1.11 R10.1 | length 336.5
  TopLayer w15: JP1.11@4403.78,8062.52 4450.58,8062.52 4473,8040.1 DL2.1@4539.3,8040.1
  BottomLayer w15: v5(4474,8047.1) 4646.36,8047.1 R10.1@4660,8033.46
LVIN2+: DL2.3 JP1.10 R11.1 | length 209.3
  TopLayer w15: JP1.10@4403.78,7953.07 4459.93,7953.07 4472.9,7940.1 DL2.3@4539.3,7940.1
  BottomLayer w15: v5(4476,7944) 4529.46,7944 R11.1@4540,7933.46
LVIN2-: DL2.4 JP1.28 R11.2 | length 343.7
  TopLayer w15: JP1.28@4273.86,7897.35 4465.65,7897.35 4473,7890 4539.2,7890 DL2.4@4539.3,7890.1
  BottomLayer w15: v5(4475,7891) 4515.54,7891 R11.2@4540,7866.54
LVIN3+: DL2.6 JP1.27 R12.2 | length 459.6
  TopLayer w15: JP1.27@4273.86,7787.9 4537.1,7787.9 DL2.6@4539.3,7790.1
  BottomLayer w15: v5(4474,7789) 4642.46,7789 R12.2@4660,7806.54
LVIN3-: DL2.5 JP1.9 R12.1 | length 342.2
  TopLayer w15: JP1.9@4403.78,7843.62 4535.78,7843.62 DL2.5@4539.3,7840.1
  BottomLayer w15: v5(4477,7843) 4495.2,7843 4506.81,7831.38 4617.92,7831.38 R12.1@4660,7873.46
LVIN4+: DL2.7 JP1.8 R13.1 | length 211.8
  TopLayer w15: JP1.8@4403.78,7734.17 4466.17,7734.17 4474,7742 4537.4,7742 DL2.7@4539.3,7740.1
  BottomLayer w15: v5(4475,7736) 4522.54,7736 R13.1@4540,7753.46
LVIN4-: DL2.8 JP1.26 R13.2 | length 341.6
  TopLayer w15: JP1.26@4273.86,7678.45 4468.45,7678.45 v5(4471,7681) 4480.1,7690.1 DL2.8@4539.3,7690.1
  BottomLayer w15: v5(4471,7681) 4534.46,7681 R13.2@4540,7686.54
LVOUT1+: DL1.15 JP1.33 | length 272.8
  BottomLayer w15: JP1.33@4273.86,8444.59 4459.41,8444.59 4472,8432 4538.8,8432 DL1.15@4540.7,8430.1
LVOUT1-: DL1.16 JP1.15 | length 145.3
  BottomLayer w15: JP1.15@4403.78,8500.32 4454.69,8500.32 4473,8482 4538.8,8482 DL1.16@4540.7,8480.1
LVOUT2+: DL1.14 JP1.14 | length 141.4
  BottomLayer w15: JP1.14@4403.78,8390.87 4468.13,8390.87 4476,8383 4537.8,8383 DL1.14@4540.7,8380.1
LVOUT2-: DL1.13 JP1.32 | length 268.9
  BottomLayer w15: JP1.32@4273.86,8335.14 4535.66,8335.14 DL1.13@4540.7,8330.1
LVOUT3+: DL1.11 JP1.31 | length 270.2
  BottomLayer w15: JP1.31@4273.86,8225.69 4467.69,8225.69 4474,8232 4538.8,8232 DL1.11@4540.7,8230.1
LVOUT3-: DL1.12 JP1.13 | length 137.5
  BottomLayer w15: JP1.13@4403.78,8281.42 4539.38,8281.42 DL1.12@4540.7,8280.1
LVOUT4+: DL1.10 JP1.12 | length 140.3
  BottomLayer w15: JP1.12@4403.78,8171.97 4467.97,8171.97 4475,8179 4539.6,8179 DL1.10@4540.7,8180.1
LVOUT4-: DL1.9 JP1.30 | length 272.6
  BottomLayer w15: JP1.30@4273.86,8116.24 4460.24,8116.24 4474.1,8130.1 DL1.9@4540.7,8130.1
LVOUT5+: JP1.25
LVOUT5-: JP1.7
LVOUT6+: JP1.6
LVOUT6-: JP1.24
LVOUT7+: JP1.23 R5.2 R6.1 | length 373.4
  TopLayer w10: JP1.23@4273.86,7350.1 4519.57,7350.1 R5.2@4537,7367.54 4635,7367.54 R6.1@4638.54,7364
LVOUT7-: JP1.5 R5.1 R7.1 | length 258.9
  TopLayer w10: JP1.5@4403.78,7405.83 4508.36,7405.83 R5.1@4537,7434.46 4566.54,7464 R7.1@4638.54,7464
LVOUT8+: JP1.22 R89.2 R92.1 | length 398.1
  TopLayer w10: JP1.22@4273.86,7240.65 4482.88,7240.65 R89.2@4537,7186.54 4563.54,7160 R92.1@4638.54,7160
LVOUT8-: JP1.4 R89.1 R93.1 | length 255.2
  TopLayer w10: JP1.4@4403.78,7296.38 4494.09,7296.38 R89.1@4537,7253.46 4632,7253.46 R93.1@4638.54,7260
NCE: JP11.6 R25.2 U1.33 | length 1631.7
  TopLayer w6: U1.33@6287.1,8303.21 6330.79,8303.21 v1(6366,8268) ; U1.33@6312.78,8301.16 cw(c6317.74,8296.2) 6317.74,8303.21 cw(c6317.74,8310.23) U1.33@6312.78,8305.27 ; v1@6361,8268 ccw(c6348.93,8268) 6357.46,8276.54 ccw(c6366,8285.07) v1@6366,8273 ; v1@6509,8118 cw(c6509,8105.93) 6517.54,8114.46 cw(c6526.07,8123) v1@6514,8123 ; v1(6509,8123) 6668,7964 6668,7877 6694,7851 6769,7851 6886.54,7733.46 R25.2@6886.54,7680 ; JP11.6@6792,7800 ccw(c6724.4,7800) 6772.2,7847.8 ccw(c6820,7895.6) JP11.6@6820,7828 ; JP11.6@6798,7800 ccw(c6744.89,7800) 6782.44,7837.56 ccw(c6820,7875.11) JP11.6@6820,7822 ; JP11.6@6804,7800 ccw(c6765.37,7800) 6792.69,7827.31 ccw(c6820,7854.63) JP11.6@6820,7816 ; JP11.6@6820,7772 cw(c6820,7704.4) 6867.8,7752.2 cw(c6915.6,7800) JP11.6@6848,7800 ; JP11.6@6820,7778 cw(c6820,7724.89) 6857.56,7762.44 cw(c6895.11,7800) JP11.6@6842,7800 ; JP11.6@6820,7784 cw(c6820,7745.37) 6847.31,7772.69 cw(c6874.63,7800) JP11.6@6836,7800 ; R25.2@6874.74,7691.8 ccw(c6846.25,7720.28) 6886.54,7720.28 ccw(c6926.82,7720.28) R25.2@6898.33,7691.8 ; R25.2@6878.98,7687.56 ccw(c6860.74,7705.8) 6886.54,7705.8 ccw(c6912.33,7705.8) R25.2@6894.09,7687.56
  BottomLayer w6: v1@6365.97,8263 cw(c6365.88,8250.93) 6374.48,8259.41 cw(c6383.07,8267.88) v1@6371,8267.97 ; v1(6366,8268) v1(6509,8123) ; v1@6504,8123.03 ccw(c6491.93,8123.12) 6500.52,8131.59 ccw(c6509.12,8140.07) v1@6509.03,8128
NCEO: U1.32
NetC24_1: C24.1 C25.1 C26.1 R41.1 R48.2 U13.2 | length 1527.5
  TopLayer w12: C24.1@7935.43,9306.31 cw(c7935.43,9278.03) 7955.43,9298.03 ; C24.1@7935.43,9333.69 ccw(c7935.43,9361.97) 7955.43,9341.97 ; C24.1@7949.11,9319.54 ccw(c7982.97,9318.41) 7959.01,9294.45 ; C24.1@7949.12,9320 cw(c7986.91,9320) 7960.19,9346.72 ; R41.1@8030.32,9283.79 ccw(c8006.96,9260.43) 8006.96,9293.46 ccw(c8006.96,9326.5) R41.1@8030.32,9303.14 ; R41.1@8040,9293.46 7960,9293.46 C24.1@7933.46,9320 7975.46,9362 8191,9362 8213.46,9339.54 C25.1@8213.46,9280 R48.2@8306.54,9280 8306.54,9256.46 ; C25.1@8203.79,9289.68 ccw(c8180.43,9313.04) 8213.46,9313.04 ccw(c8246.5,9313.04) C25.1@8223.14,9289.68 ; C25.1@8225.11,9270.32 cw(c8248.47,9246.96) 8248.47,9280 cw(c8248.47,9313.04) C25.1@8225.11,9289.68 ; R48.2@8294.89,9270.32 ccw(c8271.53,9246.96) 8271.53,9280 ccw(c8271.53,9313.04) R48.2@8294.89,9289.68 ; R48.2@8298.19,9280 ccw(c8334.86,9280) 8308.93,9254.07 ; R48.2@8299.77,9268.11 cw(c8293.14,9256.47) 8306.54,9256.47 ; R48.2@8300.22,9269.1 cw(c8290.56,9256.38) 8306.54,9256.38 cw(c8318.49,9256.38) R48.2@8313.83,9267.4 ; R48.2@8310.19,9280 ccw(c8375.83,9280) 8329.41,9233.59 ; R48.2@8313.3,9268.11 ccw(c8319.93,9256.47) 8306.54,9256.47 ; R48.2@8322.19,9280 ccw(c8416.8,9280) 8349.9,9213.1 ; C26.1@8364.62,9170.44 ccw(c8348.44,9189.53) 8373.46,9189.53 ; C26.1@8375.43,9146.31 cw(c8375.43,9118.03) 8395.43,9138.03 ; C26.1@8382.31,9170.44 cw(c8398.49,9189.53) 8373.46,9189.53 ; C26.1@8389.12,9160 ccw(c8426.91,9160) 8400.19,9133.28 ; U13.2@8485.59,9180 8485.59,9123.59 8482,9120 8413.46,9120 C26.1@8373.46,9160 8373.46,9189.54 ; 8306.54,9256.46 8373.46,9189.54
NetC24_2: C24.2 R38.1 | length 203.8
  TopLayer w12: R38.1@7856.86,9229.68 ccw(c7833.5,9253.04) 7866.54,9253.04 ccw(c7899.57,9253.04) R38.1@7876.21,9229.68 ; C24.2@7856.86,9310.32 cw(c7833.5,9286.96) 7866.54,9286.96 cw(c7899.57,9286.96) C24.2@7876.21,9310.32 ; R38.1@7866.54,9220 C24.2@7866.54,9320
NetC25_2: C25.2 R47.1 | length 203.8
  TopLayer w12: R47.1@8136.86,9189.68 ccw(c8113.5,9213.04) 8146.54,9213.04 ccw(c8179.57,9213.04) R47.1@8156.21,9189.68 ; C25.2@8136.86,9270.32 cw(c8113.5,9246.96) 8146.54,9246.96 cw(c8179.57,9246.96) C25.2@8156.21,9270.32 ; R47.1@8146.54,9180 C25.2@8146.54,9280
NetC26_2: C26.2 R47.2 U13.3 | length 717
  TopLayer w12: R47.2@8208.14,9172.71 ccw(c8238.81,9203.38) 8238.81,9160 ; R47.2@8213.46,9180 8233.46,9160 C26.2@8306.54,9160 8372.54,9094 8494,9094 8511.18,9111.18 U13.3@8511.18,9180 ; R47.2@8216.62,9181.19 ccw(c8267.79,9232.35) 8267.79,9160 ; R47.2@8216.98,9166.4 cw(c8219.11,9147.62) 8232.48,9160.99 cw(c8243.38,9171.89) R47.2@8228.58,9176.18 ; R47.2@8225.11,9189.68 ccw(c8296.76,9261.32) C26.2@8296.76,9160 ; C26.2@8294.89,9150.32 ccw(c8271.53,9126.96) 8271.53,9160 ccw(c8271.53,9193.04) C26.2@8294.89,9169.68 ; C26.2@8308.5,9146.31 cw(c8308.5,9118.03) 8328.51,9138.03 ; C26.2@8322.19,9160 ccw(c8359.98,9160) 8333.26,9133.28
NetC27_2: C27.2 U13.18 | length 363.7
  TopLayer w12: C27.2@8320,9610.88 cw(c8320,9573.09) 8346.72,9599.81 ; C27.2@8320,9626.54 8387.54,9559 8466,9559 8511.18,9513.82 U13.18@8511.18,9439.84 ; C27.2@8333.69,9624.57 ccw(c8361.97,9624.57) 8341.97,9604.57
NetC28_2: C28.2 U13.17 | length 278.7
  TopLayer w12: C28.2@8440,9610.88 cw(c8440,9588.87) 8455.57,9604.43 ; C28.2@8440,9626.54 8440,9620 8536.77,9523.23 U13.17@8536.77,9439.84 ; C28.2@8453.68,9624.57 ccw(c8497.75,9624.57) 8466.59,9593.41
NetC29_1: C29.1 C32.2 U11.V6 U14.3 | length 1396.7
  TopLayer w6: v1(8750,7522.44) U11.V6@8769.15,7503.29 ; U11.V6@8762.9,7503.29 ccw(c8747.8,7503.29) 8758.48,7513.96 ccw(c8769.15,7524.64) U11.V6@8769.15,7509.54
  TopLayer w8: C29.1@8640,8202.57 C29.1@8642.57,8200 ; C32.2@8642.57,8083.97 C32.2@8646.54,8080
  TopLayer w12: C29.1@8624.54,8178.03 cw(c8571.43,8124.93) 8646.54,8124.93 ; C29.1@8624.54,8221.97 ccw(c8581.01,8265.49) 8642.57,8265.49 ccw(c8704.12,8265.49) C29.1@8660.6,8221.97 ; U14.3@8627.54,8330.69 cw(c8591.26,8294.41) 8642.57,8294.41 ; C29.1@8633.02,8186.52 cw(c8600.4,8153.9) 8646.54,8153.9 ; C29.1@8633.02,8213.48 ccw(c8609.98,8236.52) 8642.57,8236.52 ccw(c8675.15,8236.52) C29.1@8652.11,8213.48 ; C32.2@8636.86,8070.32 cw(c8613.5,8046.96) 8646.54,8046.96 cw(c8679.57,8046.96) C32.2@8656.21,8070.32 ; C32.2@8636.86,8089.68 ccw(c8613.5,8113.04) 8646.54,8113.04 ccw(c8679.57,8113.04) C32.2@8656.21,8089.68 ; U14.3@8640,8343.15 8642.57,8340.58 C29.1@8642.57,8200 8646.54,8196.03 8646.54,7972.46 v1(8729,7890) ; 8642.57,8306.8 cw(c8676.35,8306.8) U14.3@8652.46,8330.69 ; 8646.54,8144.09 cw(c8694.54,8144.09) C29.1@8660.6,8178.03
  BottomLayer w6: v1@8725.46,7886.46 cw(c8716.93,7877.93) 8729,7877.93 cw(c8741.07,7877.93) v1@8732.54,7886.46 ; v1(8729,7890) 8729,7543.44 v1(8750,7522.44)
NetC33_2: C33.2 C34.2 FB4.2 U15.4 | length 726.9
  TopLayer w12: U15.4@8976.37,8587.25 ccw(c8935.1,8628.4) 8993.38,8628.48 ; C33.2@8983.77,8709.66 ccw(c8960.83,8732.55) 8993.23,8732.59 ; C34.2@8983.77,8804.66 ccw(c8961.15,8827.22) 8993.1,8827.26 ; C33.2@8983.79,8690.32 cw(c8960.43,8666.96) 8993.46,8666.96 cw(c9026.5,8666.96) C33.2@9003.14,8690.32 ; C34.2@8983.79,8785.32 cw(c8960.43,8761.96) 8993.46,8761.96 cw(c9026.5,8761.96) C34.2@9003.14,8785.32 ; FB4.2@8993,8896 8993.46,8570.54 U15.4@9000,8564 ; 8993.1,8828.81 ccw(c9027.23,8828.86) C34.2@9003.13,8804.69 ; 8993.23,8733.48 ccw(c9026.9,8733.53) C33.2@9003.13,8709.69 ; 8993.34,8659.99 ccw(c9096.18,8660.14) U15.4@9023.56,8587.31 ; 8993.38,8631.02 ccw(c9067.25,8631.13) U15.4@9015.09,8578.82
NetC118_1: C118.1 U13.5 | length 224
  TopLayer w12: v3@8558.12,9118.61 ccw(c8547.88,9128.85) 8562.36,9128.85 ccw(c8576.85,9128.85) v3@8566.61,9118.61 ; v3(8562.36,9114.36) U13.5@8562.36,9180
  BottomLayer w12: C118.1@8536.86,9069.68 ccw(c8513.5,9093.04) 8546.54,9093.04 ccw(c8579.57,9093.04) C118.1@8556.21,9069.68 ; C118.1@8546.54,9060 8546.54,9098.54 v3(8562.36,9114.36) ; v3@8556.36,9114.36 cw(c8541.88,9114.36) 8552.12,9104.12 cw(c8562.36,9093.88) v3@8562.36,9108.36
NetC118_2: C118.2 L1.1 U13.6 U13.7 U13.8 U13.9 U13.10 | length 122.2
  BottomLayer w12: C118.2@8603.79,9050.32 cw(c8581.55,9028.08) 8613,9028.08 ; v3@8608.76,9016.24 ccw(c8598.51,9026.49) 8613,9026.49 ccw(c8627.49,9026.49) v3@8617.24,9016.24 ; v3(8613,9012) C118.2@8613,9059.54 ; 8613,9025.84 cw(c8647.62,9025.84) C118.2@8623.14,9050.32
NetDS1_2: DS1.2 R4.1 | length 377.6
  TopLayer w8: DS1.2@4964.73,7187.33 cw(c4927.88,7150.47) 4980,7150.47 cw(c5032.12,7150.47) DS1.2@4995.27,7187.33 ; DS1.2@4970.39,7192.99 cw(c4947.19,7169.79) 4980,7169.79 cw(c5012.81,7169.79) DS1.2@4989.61,7192.99 ; v3@4974.34,7151.66 ccw(c4960.69,7165.31) 4980,7165.31 ccw(c4999.31,7165.31) v3@4985.66,7151.66 ; v3(4980,7146) DS1.2@4980,7202.6
  BottomLayer w8: v3(4980,7146) 5026.54,7192.54 ; v3@4980,7154 ccw(c4980,7173.31) 4993.66,7159.66 ccw(c5007.31,7146) v3@4988,7146 ; R4.1@5018.57,7206.49 cw(c5010.34,7192.54) 5026.54,7192.54 ; R4.1@5026.54,7220 5026.54,7192.54 ; R4.1@5034.5,7206.49 ccw(c5042.74,7192.54) 5026.54,7192.54
NetDS2_2: DS2.2 R16.1 | length 391
  TopLayer w8: DS2.2@5100,7002.6 5138.6,7002.6 ; DS2.2@5125.76,6994.12 cw(c5138.6,6988.64) 5138.6,7002.6 ; DS2.2@5125.76,7011.07 ccw(c5138.6,7016.55) 5138.6,7002.6 ; v3@5181.34,7135.34 cw(c5167.69,7121.69) 5187,7121.69 cw(c5206.31,7121.69) v3@5192.66,7135.34 ; v3(5187,7141) 5187,7051 5138.6,7002.6
  BottomLayer w8: R16.1@5175.44,7111.09 ccw(c5148.67,7137.87) 5186.54,7137.87 ccw(c5224.4,7137.87) R16.1@5197.63,7111.09 ; v3@5181.34,7135.34 cw(c5168.81,7122.81) 5186.54,7122.81 ; R16.1@5186.54,7100 5186.54,7140.54 v3(5187,7141) ; 5186.54,7120.56 cw(c5207.44,7120.56) v3@5192.66,7135.34
NetDS3_2: DS3.2 R17.1 | length 353
  TopLayer w8: DS3.2@5100,7202.6 5160.4,7202.6 ; DS3.2@5115.52,7192.99 cw(c5138.72,7169.79) 5138.72,7202.6 cw(c5138.72,7235.41) DS3.2@5115.52,7212.21 ; DS3.2@5121.17,7187.33 cw(c5158.03,7150.47) 5158.03,7202.6 cw(c5158.03,7254.72) DS3.2@5121.17,7217.86 ; v3@5166,7189.03 ccw(c5146.89,7189.09) 5160.4,7202.6 ; v3@5173.97,7197 cw(c5173.91,7216.11) 5160.4,7202.6 ; v3(5174,7189) 5160.4,7202.6
  BottomLayer w8: v3@5168.53,7194.84 ccw(c5156.69,7207.46) R17.1@5174,7207.46 ; v3@5174,7187.25 cw(c5191.87,7187.25) R17.1@5187.98,7204.69 ; v3(5174,7189) R17.1@5174,7207.46 ; v3@5174,7197.23 cw(c5189.64,7197.23) R17.1@5186.24,7212.5 ; v3@5179.47,7194.84 cw(c5191.31,7207.46) R17.1@5174,7207.46 ; R17.1@5186.54,7220 R17.1@5174,7207.46
NetDS4_1: DS4.1 R51.2 | length 376.5
  TopLayer w6: DS4.1@8801.26,6501.71 ccw(c8769.51,6532.81) 8813.95,6533.27 ; R51.2@8803.76,6568.08 cw(c8780.28,6544.1) 8813.83,6544.45 ; DS4.1@8805.55,6497.51 ccw(c8784.15,6518.48) 8814.1,6518.79 ; R51.2@8807.96,6572.37 cw(c8794.61,6558.74) 8813.68,6558.94 ; R51.2@8813.46,6580 DS4.1@8814.46,6483.94 ; 8813.8,6547.55 ccw(c8878.43,6548.22) DS4.1@8833.21,6502.04 ; 8813.78,6549.43 cw(c8846.3,6549.77) R51.2@8823.07,6572.52 ; 8813.95,6533.06 ccw(c8864.1,6533.59) DS4.1@8829.01,6497.76 ; 8813.93,6534.95 cw(c8860.93,6535.44) R51.2@8827.35,6568.33 ; 8814.1,6518.58 ccw(c8849.77,6518.95) DS4.1@8824.81,6493.47
NetDS5_1: DS5.1 R57.1 | length 275.3
  TopLayer w12: DS5.1@8786.15,8811.25 ccw(c8752.7,8844.7) 8800,8844.7 ccw(c8847.3,8844.7) DS5.1@8813.85,8811.25 ; R57.1@8790.32,8934.89 cw(c8766.96,8911.53) 8800,8911.53 cw(c8833.04,8911.53) R57.1@8809.68,8934.89 ; DS5.1@8800,8797.4 R57.1@8800,8946.54
NetDS6_2: DS6.2 R88.1 | length 434.4
  TopLayer w8: DS6.2@4980,7002.6 v3(5035.6,7002.6) ; DS6.2@4995.84,6993.32 cw(c5017.18,6973.4) 5017.18,7002.6 cw(c5017.18,7031.79) DS6.2@4995.84,7011.87 ; DS6.2@5001.69,6987.86 cw(c5035.59,6956.21) v3(5035.6,7002.6) ; DS6.2@5001.69,7017.33 ccw(c5035.59,7048.98) v3(5035.6,7002.6) ; v3@5029.94,6996.94 ccw(c5016.28,6983.28) 5016.28,7002.6 ccw(c5016.28,7021.91) v3@5029.94,7008.25
  BottomLayer w8: R88.1@5017.41,7088.91 cw(c4973.51,7045.01) 5035.6,7045.01 ; R88.1@5023.07,7094.57 cw(c4992.83,7064.32) 5035.6,7064.32 ; R88.1@5026.54,7100 5035.6,7090.94 v3(5035.6,7002.6) ; v3@5029.94,7008.25 ccw(c5016.28,7021.91) 5035.6,7021.91 ccw(c5054.91,7021.91) v3@5041.25,7008.25 ; 5035.6,7079.26 cw(c5049.25,7079.26) R88.1@5039.59,7088.91
NetJ3_1: 
NetJP13_1: JP13.1 R85.1 | length 329.3
  BottomLayer w8: R85.1@9245.46,8890 JP13.1@9352,8890 ; R85.1@9258.52,8878.91 cw(c9285.3,8852.13) 9285.3,8890 cw(c9285.3,8927.87) R85.1@9258.52,8901.09 ; JP13.1@9333.95,8871.95 ccw(c9290.37,8828.37) 9290.37,8890 ccw(c9290.37,8951.63) JP13.1@9333.95,8908.05 ; JP13.1@9339.61,8877.61 ccw(c9309.68,8847.68) 9309.68,8890 ccw(c9309.68,8932.32) JP13.1@9339.61,8902.39
NetJP13_2: JP13.2 R62.2 | length 329.3
  TopLayer w8: JP13.2@9452,8890 R62.2@9558.54,8890 ; JP13.2@9464.39,8877.61 cw(c9494.32,8847.68) 9494.32,8890 cw(c9494.32,8932.32) JP13.2@9464.39,8902.39 ; JP13.2@9470.05,8871.95 cw(c9513.63,8828.37) 9513.63,8890 cw(c9513.63,8951.63) JP13.2@9470.05,8908.05 ; R62.2@9545.48,8878.91 ccw(c9518.7,8852.13) 9518.7,8890 ccw(c9518.7,8927.87) R62.2@9545.48,8901.09
NetJP13_3: JP13.3 R87.1 | length 329.3
  BottomLayer w8: R87.1@9245.46,8790 JP13.3@9352,8790 ; R87.1@9258.52,8778.91 cw(c9285.3,8752.13) 9285.3,8790 cw(c9285.3,8827.87) R87.1@9258.52,8801.09 ; JP13.3@9333.95,8771.95 ccw(c9290.37,8728.37) 9290.37,8790 ccw(c9290.37,8851.63) JP13.3@9333.95,8808.05 ; JP13.3@9339.61,8777.61 ccw(c9309.68,8747.68) 9309.68,8790 ccw(c9309.68,8832.32) JP13.3@9339.61,8802.39
NetJP13_4: JP13.4 R61.2 | length 329.3
  TopLayer w8: JP13.4@9452,8790 R61.2@9558.54,8790 ; JP13.4@9464.39,8777.61 cw(c9494.32,8747.68) 9494.32,8790 cw(c9494.32,8832.32) JP13.4@9464.39,8802.39 ; JP13.4@9470.05,8771.95 cw(c9513.63,8728.37) 9513.63,8790 cw(c9513.63,8851.63) JP13.4@9470.05,8808.05 ; R61.2@9545.48,8778.91 ccw(c9518.7,8752.13) 9518.7,8790 ccw(c9518.7,8827.87) R61.2@9545.48,8801.09
NetJP13_5: JP13.5 R86.1 | length 329.3
  BottomLayer w8: R86.1@9245.46,8690 JP13.5@9352,8690 ; R86.1@9258.52,8678.91 cw(c9285.3,8652.13) 9285.3,8690 cw(c9285.3,8727.87) R86.1@9258.52,8701.09 ; JP13.5@9333.95,8671.95 ccw(c9290.37,8628.37) 9290.37,8690 ccw(c9290.37,8751.63) JP13.5@9333.95,8708.05 ; JP13.5@9339.61,8677.61 ccw(c9309.68,8647.68) 9309.68,8690 ccw(c9309.68,8732.32) JP13.5@9339.61,8702.39
NetJP13_6: JP13.6 R60.2 | length 329.3
  TopLayer w8: JP13.6@9452,8690 R60.2@9558.54,8690 ; JP13.6@9464.39,8677.61 cw(c9494.32,8647.68) 9494.32,8690 cw(c9494.32,8732.32) JP13.6@9464.39,8702.39 ; JP13.6@9470.05,8671.95 cw(c9513.63,8628.37) 9513.63,8690 cw(c9513.63,8751.63) JP13.6@9470.05,8708.05 ; R60.2@9545.48,8678.91 ccw(c9518.7,8652.13) 9518.7,8690 ccw(c9518.7,8727.87) R60.2@9545.48,8701.09
NetJP13_7: JP13.7 R84.1 | length 329.3
  BottomLayer w8: R84.1@9245.46,8590 JP13.7@9352,8590 ; R84.1@9258.52,8578.91 cw(c9285.3,8552.13) 9285.3,8590 cw(c9285.3,8627.87) R84.1@9258.52,8601.09 ; JP13.7@9333.95,8571.95 ccw(c9290.37,8528.37) 9290.37,8590 ccw(c9290.37,8651.63) JP13.7@9333.95,8608.05 ; JP13.7@9339.61,8577.61 ccw(c9309.68,8547.68) 9309.68,8590 ccw(c9309.68,8632.32) JP13.7@9339.61,8602.39
NetJP13_8: JP13.8 R59.2 | length 329.3
  TopLayer w8: JP13.8@9452,8590 R59.2@9558.54,8590 ; JP13.8@9464.39,8577.61 cw(c9494.32,8547.68) 9494.32,8590 cw(c9494.32,8632.32) JP13.8@9464.39,8602.39 ; JP13.8@9470.05,8571.95 cw(c9513.63,8528.37) 9513.63,8590 cw(c9513.63,8651.63) JP13.8@9470.05,8608.05 ; R59.2@9545.48,8578.91 ccw(c9518.7,8552.13) 9518.7,8590 ccw(c9518.7,8627.87) R59.2@9545.48,8601.09
NetJP13_9: JP13.9 R83.1 | length 329.3
  BottomLayer w8: R83.1@9245.46,8490 JP13.9@9352,8490 ; R83.1@9258.52,8478.91 cw(c9285.3,8452.13) 9285.3,8490 cw(c9285.3,8527.87) R83.1@9258.52,8501.09 ; JP13.9@9333.95,8471.95 ccw(c9290.37,8428.37) 9290.37,8490 ccw(c9290.37,8551.63) JP13.9@9333.95,8508.05 ; JP13.9@9339.61,8477.61 ccw(c9309.68,8447.68) 9309.68,8490 ccw(c9309.68,8532.32) JP13.9@9339.61,8502.39
NetJP13_10: JP13.10 R58.2 | length 329.3
  TopLayer w8: JP13.10@9452,8490 R58.2@9558.54,8490 ; JP13.10@9464.39,8477.61 cw(c9494.32,8447.68) 9494.32,8490 cw(c9494.32,8532.32) JP13.10@9464.39,8502.39 ; JP13.10@9470.05,8471.95 cw(c9513.63,8428.37) 9513.63,8490 cw(c9513.63,8551.63) JP13.10@9470.05,8508.05 ; R58.2@9545.48,8478.91 ccw(c9518.7,8452.13) 9518.7,8490 ccw(c9518.7,8527.87) R58.2@9545.48,8501.09
NetQ1_1: Q1.1 R46.1 U7.1 | length 1294.2
  TopLayer w12: U7.1@7193.44,9633.44 cw(c7225.87,9665.87) 7180,9665.87 cw(c7134.13,9665.87) 7166.56,9633.44 U7.1@7180,9620 7180,9694 7255,9769 7918,9769 7940,9747 Q1.1@7940,9709.21 7949.21,9700 R46.1@8086.54,9700 ; Q1.1@7931.72,9724.78 ccw(c7911.71,9744.78) 7940,9744.78 ccw(c7968.29,9744.78) Q1.1@7948.28,9724.78 ; Q1.1@7948.28,9693.64 cw(c7963.63,9678.3) 7963.63,9700 ; Q1.1@7948.28,9710.21 ccw(c7972.94,9734.87) 7972.94,9700 ; R46.1@8074.89,9690.32 ccw(c8051.53,9666.96) 8051.53,9700 ccw(c8051.53,9733.04) R46.1@8074.89,9709.68
NetQ1_2: Q1.2 R39.1 | length 208.7
  TopLayer w12: Q1.2@7894.31,9601.52 cw(c7874.31,9581.52) 7902.6,9581.52 cw(c7930.88,9581.52) Q1.2@7910.88,9601.52 ; R39.1@7894.89,9509.68 ccw(c7876.28,9528.29) 7902.6,9528.29 ; 7902.6,9537.79 ccw(c7942.36,9537.79) R39.1@7914.24,9509.68 ; Q1.2@7902.6,9610.79 7902.6,9503.94 R39.1@7906.54,9500
NetR6_2: R6.2 U1.178 | length 476.6
  TopLayer w10: R6.2@4705.46,7364 4833,7491.54 4833,7684 4861.66,7712.66 U1.178@4924.9,7712.66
